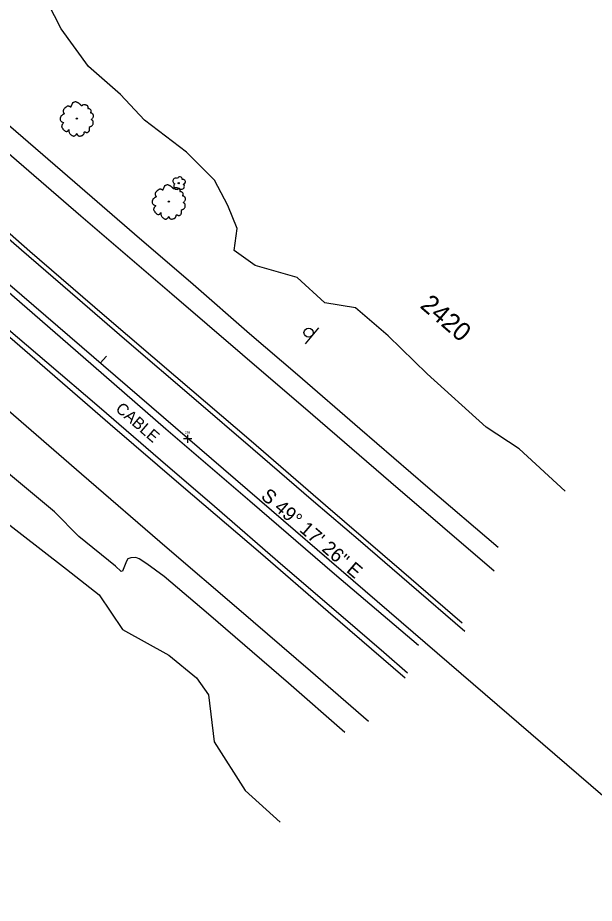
# Model space of a CAD drawing. Extents: x 2076109 to 2080761, y 592812 to 596750.
# Drawn here: x 2080011.7 to 2080260.2, y 593194 to 593575.6 of the extents above; entities that cross this region are included whole.
import ezdxf

# ---------------------------------------------------------------- set-up
doc = ezdxf.new("R2010")
doc.units = 0
for name, color, linetype in [('Default', 7, 'Continuous'), ('RD_EX_BldgApp', 7, 'Continuous'), ('RD_EX_GuardRail', 7, 'Continuous'), ('RD_EX_GuardRail_txCode', 7, 'Continuous'), ('RD_EX_Misc', 7, 'Continuous'), ('RD_EX_Road', 7, 'Continuous'), ('RD_EX_VEG', 7, 'Continuous'), ('RD_HC_Cl', 7, 'Continuous'), ('RD_HC_Data', 7, 'Continuous'), ('RD_HC_Data_Tic', 7, 'Continuous'), ('RD_HC_TX_Sta50', 7, 'Continuous')]:
    doc.layers.add(name, color=color, linetype=linetype)

msp = doc.modelspace()

# ---------------------------------------------------------------- linework, layer by layer
at = {"layer": 'Default'}
for p, q in [((2080084.9, 593395.9), (2080084.9, 593392.4)), ((2080084.9, 593395.9), (2080084.9, 593392.4)), ((2080086.65, 593394.15), (2080083.15, 593394.15)), ((2080086.65, 593394.15), (2080083.15, 593394.15))]:
    msp.add_line(p, q, dxfattribs=at)
at = {"layer": 'RD_EX_BldgApp'}
msp.add_line((2080135.68, 593435.15), (2080141.49, 593442.02), dxfattribs=at)
msp.add_line((2080135.68, 593435.15), (2080141.49, 593442.02), dxfattribs=at)
msp.add_circle((2080137.05, 593439.9), 2, dxfattribs=at)
msp.add_circle((2080137.05, 593439.9), 2, dxfattribs=at)
at = {"layer": 'RD_EX_GuardRail'}
msp.add_lwpolyline([(2080184.35, 593305.04), (2080148.2, 593335.86), (2080111.67, 593367.26), (2080075.44, 593398.3), (2080039.84, 593429.28), (2080003.46, 593460.74), (2079967.36, 593491.67), (2079919.17, 593532.83), (2079871.19, 593574.23), (2079835.53, 593605.02), (2079799.41, 593635.93), (2079763.16, 593666.95), (2079727.5, 593697.27), (2079690.37, 593729.2), (2079655.55, 593758.99), (2079608.01, 593799.67)], dxfattribs=at)
at = {"layer": 'RD_EX_Misc'}
for points in [[(2080217.04, 593337.18), (2080172.52, 593375.33), (2080138.87, 593404.33), (2080108.48, 593430.29), (2080078.14, 593456.52), (2080038.92, 593490.11), (2080009.05, 593515.98), (2079977.29, 593543.26), (2079946.15, 593570.28), (2079919.11, 593593.43), (2079890.41, 593617.97), (2079858.75, 593645.26), (2079821.86, 593677.15), (2079782.12, 593711.42), (2079735.64, 593751.71), (2079701.45, 593781.37), (2079664.35, 593813.72), (2079643.76, 593831.64)], [(2079627.11, 593812.28), (2079655.96, 593786.97), (2079692.98, 593754.86), (2079726.56, 593725.77), (2079758.83, 593697.63), (2079788.04, 593672.28), (2079811.24, 593652.3), (2079842, 593625.98), (2079868.07, 593603.53), (2079898.03, 593577.49), (2079923.97, 593555.11), (2079945.84, 593536.38), (2079972.92, 593513.01), (2079994.98, 593494.07), (2080016.85, 593475.02), (2080049.11, 593447.31), (2080079.81, 593420.95), (2080112.25, 593393.22), (2080144.25, 593365.64), (2080177.02, 593337.45), (2080203.16, 593314.91)], [(2080178.72, 593290.98), (2080145.52, 593319.67), (2080116.25, 593344.84), (2080082.12, 593374.03), (2080051.53, 593400.34), (2080021.2, 593426.66), (2079989.82, 593453.61), (2079954.27, 593484.21), (2079917.77, 593515.59), (2079872.88, 593554.03), (2079843.75, 593579.04), (2079811.01, 593607.11), (2079771.89, 593640.76), (2079736.28, 593671.46), (2079708.41, 593695.19), (2079678.65, 593720.6), (2079637.6, 593755.82), (2079606.82, 593782.2)], [(2079590.1, 593765.16), (2079617.13, 593742.26), (2079645.39, 593718.11), (2079673.76, 593693.67), (2079705.98, 593665.94), (2079741.28, 593635.42), (2079768.01, 593612.45), (2079794.32, 593589.74), (2079821.72, 593566.1), (2079850.25, 593541.52), (2079880.79, 593515.25), (2079909.32, 593490.67), (2079940.4, 593463.94), (2079966.11, 593441.94), (2079995.57, 593416.65), (2080039.13, 593379.08), (2080076.01, 593347.24), (2080106.97, 593320.7), (2080137.83, 593294.2), (2080162.8, 593272.51)]]:
    msp.add_lwpolyline(points, dxfattribs=at)
at = {"layer": 'RD_EX_Road'}
for points in [[(2079847.19, 593579.3), (2079876.99, 593553.77), (2079900.24, 593533.48), (2079923.68, 593513.62), (2079949.41, 593491.47), (2079974.36, 593470.03), (2079998.83, 593448.69), (2080024.15, 593427.25), (2080046.72, 593407.88), (2080073.17, 593385.13), (2080096.5, 593365.09), (2080125.99, 593339.59), (2080151.99, 593317.38), (2080169.44, 593302.21), (2080179.69, 593293.27)], [(2080204.43, 593311.21), (2080180.43, 593331.76), (2080159.45, 593349.86), (2080139.19, 593367.19), (2080113.07, 593389.68), (2080087.59, 593411.58), (2080058.73, 593436.21), (2080034.27, 593457.36), (2080013.24, 593475.51), (2079982.05, 593502.38), (2079952.67, 593527.69), (2079915.58, 593559.4), (2079891.77, 593580.17)], [(2079952.79, 593576.41), (2079973.53, 593558.52), (2079991.07, 593543.66), (2080010.86, 593526.69), (2080036.29, 593504.75), (2080061.97, 593482.54), (2080087.26, 593460.81), (2080111.58, 593439.6), (2080132.18, 593421.92), (2080159.11, 593398.54), (2080188.43, 593373.33), (2080218.73, 593347.44)], [(2080152.72, 593267.66), (2080128.39, 593288.81), (2080093.85, 593318.54), (2080074.78, 593334.89), (2080067.34, 593340.26), (2080064, 593342.46), (2080062.54, 593343.07), (2080060.4, 593342.84), (2080059.08, 593342.5), (2080058.49, 593341.44), (2080056.81, 593337.09), (2080056.21, 593336.92), (2080053.82, 593339.36), (2080038, 593352.02), (2080027.51, 593362.71), (2080013.69, 593374.25), (2079994.53, 593390.12)]]:
    msp.add_lwpolyline(points, dxfattribs=at)
at = {"layer": 'RD_EX_VEG'}
for points in [[(2080247.68, 593371.56), (2080227.73, 593389.81), (2080213.63, 593399.22), (2080188.12, 593422.2), (2080171.34, 593438.57), (2080157.25, 593450.56), (2080143.98, 593452.78), (2080132.06, 593463.64), (2080114, 593468.88), (2080104.89, 593475.28), (2080106.2, 593484.71), (2080102.2, 593494.65), (2080096.44, 593505.56), (2080084.44, 593517.6), (2080066.35, 593531.39), (2080055.91, 593542.46), (2080042.12, 593554.57), (2080030.41, 593570.81), (2080021.61, 593588.05), (2080015.74, 593597.76)], [(2079741.28, 593586.6), (2079759.63, 593573.33), (2079766.05, 593568.33), (2079784.04, 593551.85), (2079798.13, 593538.37), (2079815.23, 593521.73), (2079829.05, 593516.08), (2079860.88, 593485.4), (2079888.13, 593460.36), (2079900, 593443.24), (2079927, 593427.12), (2079947.52, 593409.93), (2079973.96, 593389.29), (2080002.41, 593361.36), (2080032.72, 593337.93), (2080046.73, 593326.92), (2080056.76, 593311.95), (2080076.73, 593300.98), (2080088.77, 593291.13), (2080093.96, 593283.85), (2080096.32, 593263.66), (2080109.67, 593242.67), (2080124.71, 593229.03)]]:
    msp.add_lwpolyline(points, dxfattribs=at)
for centre, radius in [((2080037.12, 593532.12), 0.25), ((2080037.12, 593532.12), 0.25), ((2080037.1, 593532.12), 0.0001), ((2080037.1, 593532.12), 0.0001), ((2080081.06, 593504.32), 0.25), ((2080081.06, 593504.32), 0.25), ((2080076.77, 593496.36), 0.25), ((2080076.77, 593496.36), 0.25), ((2080076.75, 593496.35), 0.0001), ((2080076.75, 593496.35), 0.0001)]:
    msp.add_circle(centre, radius, dxfattribs=at)
for centre, radius, start, end in [((2080079.78, 593505.22), 1.26, 55.6193, 253.9015), ((2080079.78, 593505.22), 1.26, 55.6193, 253.9015), ((2080081.53, 593505.96), 1.08, 354.1438, 163.9235), ((2080081.53, 593505.96), 1.08, 354.1438, 163.9235), ((2080082.97, 593504.92), 0.995, 267.9301, 111.2143), ((2080082.97, 593504.92), 0.995, 267.9301, 111.2143), ((2080080.2, 593502.95), 1.32, 126.0502, 324.9265), ((2080080.2, 593502.95), 1.32, 126.0502, 324.9265), ((2080082.27, 593502.9), 1.22, 215.7342, 57.2722), ((2080082.27, 593502.9), 1.22, 215.7342, 57.2722)]:
    msp.add_arc(centre, radius, start, end, dxfattribs=at)
for points in [[(2080041.91, 593537.46), (2080041.7, 593537.68), (2080041.39, 593537.81), (2080041.13, 593537.9), (2080040.91, 593537.99), (2080040.68, 593538.06), (2080040.34, 593538.13), (2080040.03, 593538.12), (2080039.78, 593538.01), (2080039.59, 593537.88), (2080039.37, 593537.7), (2080039.26, 593537.57), (2080039.15, 593537.63), (2080039.05, 593537.75), (2080038.91, 593537.97), (2080038.72, 593538.13), (2080038.53, 593538.3), (2080038.25, 593538.51), (2080037.99, 593538.73), (2080037.75, 593538.88), (2080037.47, 593539.05), (2080037.1, 593539.2), (2080036.76, 593539.34), (2080036.37, 593539.34), (2080035.87, 593539.15), (2080035.54, 593538.96), (2080035.27, 593538.87), (2080035.09, 593538.43), (2080034.99, 593538.05), (2080034.88, 593537.89), (2080034.66, 593537.52), (2080034.59, 593537.28), (2080034.55, 593537.05), (2080034.48, 593537.08), (2080034.16, 593537.29), (2080033.87, 593537.41), (2080033.4, 593537.51), (2080033.08, 593537.49), (2080032.79, 593537.31), (2080032.55, 593537.06), (2080032.34, 593536.98), (2080032.1, 593536.82), (2080032.04, 593536.78), (2080031.79, 593536.56), (2080031.57, 593536.16), (2080031.36, 593535.88), (2080031.31, 593535.62), (2080031.3, 593535.39), (2080031.27, 593535.09), (2080031.43, 593534.66), (2080031.61, 593534.37), (2080031.74, 593534.22), (2080031.28, 593533.96), (2080031.02, 593533.73), (2080030.66, 593533.51), (2080030.61, 593533.45), (2080030.27, 593533.12), (2080030.17, 593532.78), (2080029.98, 593532.45), (2080029.96, 593532.16), (2080029.97, 593531.75), (2080030.07, 593531.37), (2080030.37, 593530.95), (2080030.69, 593530.71), (2080031.24, 593530.46), (2080031.48, 593530.36), (2080031.34, 593530.24), (2080031.12, 593529.94), (2080030.84, 593529.62), (2080030.74, 593529.28), (2080030.64, 593529), (2080030.59, 593528.72), (2080030.68, 593528.33), (2080030.94, 593528.02), (2080031.16, 593527.62), (2080031.45, 593527.27), (2080031.81, 593526.93), (2080032.37, 593526.65), (2080032.66, 593526.56), (2080032.85, 593526.63), (2080033.24, 593526.78), (2080033.35, 593526.99), (2080033.76, 593527.42), (2080033.72, 593527.23), (2080033.63, 593526.85), (2080033.81, 593526.29), (2080034, 593525.9), (2080034.26, 593525.48), (2080034.44, 593525.22), (2080034.85, 593524.97), (2080035.18, 593524.78), (2080035.54, 593524.63), (2080035.95, 593524.64), (2080036.26, 593524.74), (2080036.48, 593524.91), (2080036.78, 593525.15), (2080036.93, 593525.25)], [(2080041.91, 593537.46), (2080041.7, 593537.68), (2080041.39, 593537.81), (2080041.13, 593537.9), (2080040.91, 593537.99), (2080040.68, 593538.06), (2080040.34, 593538.13), (2080040.03, 593538.12), (2080039.78, 593538.01), (2080039.59, 593537.88), (2080039.37, 593537.7), (2080039.26, 593537.57), (2080039.15, 593537.63), (2080039.05, 593537.75), (2080038.91, 593537.97), (2080038.72, 593538.13), (2080038.53, 593538.3), (2080038.25, 593538.51), (2080037.99, 593538.73), (2080037.75, 593538.88), (2080037.47, 593539.05), (2080037.1, 593539.2), (2080036.76, 593539.34), (2080036.37, 593539.34), (2080035.87, 593539.15), (2080035.54, 593538.96), (2080035.27, 593538.87), (2080035.09, 593538.43), (2080034.99, 593538.05), (2080034.88, 593537.89), (2080034.66, 593537.52), (2080034.59, 593537.28), (2080034.55, 593537.05), (2080034.48, 593537.08), (2080034.16, 593537.29), (2080033.87, 593537.41), (2080033.4, 593537.51), (2080033.08, 593537.49), (2080032.79, 593537.31), (2080032.55, 593537.06), (2080032.34, 593536.98), (2080032.1, 593536.82), (2080032.04, 593536.78), (2080031.79, 593536.56), (2080031.57, 593536.16), (2080031.36, 593535.88), (2080031.31, 593535.62), (2080031.3, 593535.39), (2080031.27, 593535.09), (2080031.43, 593534.66), (2080031.61, 593534.37), (2080031.74, 593534.22), (2080031.28, 593533.96), (2080031.02, 593533.73), (2080030.66, 593533.51), (2080030.61, 593533.45), (2080030.27, 593533.12), (2080030.17, 593532.78), (2080029.98, 593532.45), (2080029.96, 593532.16), (2080029.97, 593531.75), (2080030.07, 593531.37), (2080030.37, 593530.95), (2080030.69, 593530.71), (2080031.24, 593530.46), (2080031.48, 593530.36), (2080031.34, 593530.24), (2080031.12, 593529.94), (2080030.84, 593529.62), (2080030.74, 593529.28), (2080030.64, 593529), (2080030.59, 593528.72), (2080030.68, 593528.33), (2080030.94, 593528.02), (2080031.16, 593527.62), (2080031.45, 593527.27), (2080031.81, 593526.93), (2080032.37, 593526.65), (2080032.66, 593526.56), (2080032.85, 593526.63), (2080033.24, 593526.78), (2080033.35, 593526.99), (2080033.76, 593527.42), (2080033.72, 593527.23), (2080033.63, 593526.85), (2080033.81, 593526.29), (2080034, 593525.9), (2080034.26, 593525.48), (2080034.44, 593525.22), (2080034.85, 593524.97), (2080035.18, 593524.78), (2080035.54, 593524.63), (2080035.95, 593524.64), (2080036.26, 593524.74), (2080036.48, 593524.91), (2080036.78, 593525.15), (2080036.93, 593525.25)], [(2080036.93, 593525.25), (2080036.99, 593525.43), (2080037.12, 593525.65), (2080037.16, 593525.58), (2080037.26, 593525.43), (2080037.38, 593525.15), (2080037.5, 593524.95), (2080037.77, 593524.76), (2080038.04, 593524.65), (2080038.56, 593524.57), (2080039.08, 593524.75), (2080039.55, 593524.87), (2080039.82, 593525.07), (2080039.93, 593525.27), (2080040.23, 593525.66), (2080040.25, 593525.98), (2080040.29, 593526.11), (2080040.48, 593526.48), (2080040.57, 593526.47), (2080040.81, 593526.32), (2080041.17, 593526.17), (2080041.46, 593526.09), (2080041.75, 593526.07), (2080041.95, 593526.2), (2080042.19, 593526.51), (2080042.49, 593526.78), (2080042.53, 593526.95), (2080042.55, 593527.13), (2080042.63, 593527.33), (2080042.61, 593527.54), (2080042.64, 593527.72), (2080042.63, 593527.86), (2080042.63, 593528.05), (2080042.58, 593528.26), (2080042.5, 593528.4), (2080042.56, 593528.54), (2080042.8, 593528.6), (2080042.9, 593528.64), (2080043.07, 593528.79), (2080043.47, 593528.91), (2080043.77, 593529.18), (2080044.01, 593529.53), (2080044.15, 593529.78), (2080044.22, 593530.08), (2080044.23, 593530.4), (2080044.25, 593530.62), (2080044.2, 593530.82), (2080044.03, 593531.13), (2080043.88, 593531.33), (2080043.61, 593531.56), (2080043.49, 593531.73), (2080043.55, 593531.75), (2080043.64, 593531.86), (2080043.82, 593532.07), (2080044.06, 593532.46), (2080044.27, 593532.94), (2080044.29, 593532.96), (2080044.38, 593533.21), (2080044.34, 593533.51), (2080044.27, 593533.7), (2080044.2, 593533.92), (2080044.03, 593534.11), (2080043.8, 593534.3), (2080043.56, 593534.44), (2080043.35, 593534.5), (2080043.13, 593534.52), (2080043.17, 593534.68), (2080043.29, 593534.97), (2080043.35, 593535.12), (2080043.35, 593535.35), (2080043.32, 593535.65), (2080043.06, 593536.04), (2080042.53, 593536.39), (2080042.18, 593536.43), (2080041.95, 593536.4), (2080041.99, 593536.53), (2080041.97, 593536.81), (2080042.01, 593537.01), (2080041.96, 593537.22), (2080041.91, 593537.39), (2080041.87, 593537.49)], [(2080036.93, 593525.25), (2080036.99, 593525.43), (2080037.12, 593525.65), (2080037.16, 593525.58), (2080037.26, 593525.43), (2080037.38, 593525.15), (2080037.5, 593524.95), (2080037.77, 593524.76), (2080038.04, 593524.65), (2080038.56, 593524.57), (2080039.08, 593524.75), (2080039.55, 593524.87), (2080039.82, 593525.07), (2080039.93, 593525.27), (2080040.23, 593525.66), (2080040.25, 593525.98), (2080040.29, 593526.11), (2080040.48, 593526.48), (2080040.57, 593526.47), (2080040.81, 593526.32), (2080041.17, 593526.17), (2080041.46, 593526.09), (2080041.75, 593526.07), (2080041.95, 593526.2), (2080042.19, 593526.51), (2080042.49, 593526.78), (2080042.53, 593526.95), (2080042.55, 593527.13), (2080042.63, 593527.33), (2080042.61, 593527.54), (2080042.64, 593527.72), (2080042.63, 593527.86), (2080042.63, 593528.05), (2080042.58, 593528.26), (2080042.5, 593528.4), (2080042.56, 593528.54), (2080042.8, 593528.6), (2080042.9, 593528.64), (2080043.07, 593528.79), (2080043.47, 593528.91), (2080043.77, 593529.18), (2080044.01, 593529.53), (2080044.15, 593529.78), (2080044.22, 593530.08), (2080044.23, 593530.4), (2080044.25, 593530.62), (2080044.2, 593530.82), (2080044.03, 593531.13), (2080043.88, 593531.33), (2080043.61, 593531.56), (2080043.49, 593531.73), (2080043.55, 593531.75), (2080043.64, 593531.86), (2080043.82, 593532.07), (2080044.06, 593532.46), (2080044.27, 593532.94), (2080044.29, 593532.96), (2080044.38, 593533.21), (2080044.34, 593533.51), (2080044.27, 593533.7), (2080044.2, 593533.92), (2080044.03, 593534.11), (2080043.8, 593534.3), (2080043.56, 593534.44), (2080043.35, 593534.5), (2080043.13, 593534.52), (2080043.17, 593534.68), (2080043.29, 593534.97), (2080043.35, 593535.12), (2080043.35, 593535.35), (2080043.32, 593535.65), (2080043.06, 593536.04), (2080042.53, 593536.39), (2080042.18, 593536.43), (2080041.95, 593536.4), (2080041.99, 593536.53), (2080041.97, 593536.81), (2080042.01, 593537.01), (2080041.96, 593537.22), (2080041.91, 593537.39), (2080041.87, 593537.49)], [(2080081.56, 593501.69), (2080081.35, 593501.91), (2080081.04, 593502.04), (2080080.78, 593502.13), (2080080.56, 593502.22), (2080080.33, 593502.29), (2080079.99, 593502.36), (2080079.69, 593502.35), (2080079.43, 593502.25), (2080079.24, 593502.11), (2080079.03, 593501.93), (2080078.91, 593501.8), (2080078.8, 593501.86), (2080078.7, 593501.98), (2080078.56, 593502.2), (2080078.37, 593502.36), (2080078.18, 593502.53), (2080077.9, 593502.74), (2080077.64, 593502.97), (2080077.4, 593503.11), (2080077.12, 593503.28), (2080076.75, 593503.43), (2080076.41, 593503.57), (2080076.02, 593503.57), (2080075.52, 593503.38), (2080075.19, 593503.19), (2080074.92, 593503.1), (2080074.74, 593502.67), (2080074.64, 593502.29), (2080074.53, 593502.12), (2080074.31, 593501.75), (2080074.24, 593501.51), (2080074.2, 593501.28), (2080074.13, 593501.31), (2080073.81, 593501.52), (2080073.52, 593501.64), (2080073.05, 593501.75), (2080072.73, 593501.72), (2080072.45, 593501.54), (2080072.2, 593501.29), (2080071.99, 593501.21), (2080071.75, 593501.05), (2080071.69, 593501.01), (2080071.44, 593500.79), (2080071.22, 593500.39), (2080071.01, 593500.11), (2080070.96, 593499.86), (2080070.95, 593499.63), (2080070.92, 593499.32), (2080071.08, 593498.89), (2080071.26, 593498.6), (2080071.39, 593498.45), (2080070.94, 593498.19), (2080070.67, 593497.96), (2080070.31, 593497.74), (2080070.26, 593497.68), (2080069.92, 593497.35), (2080069.82, 593497.01), (2080069.63, 593496.68), (2080069.61, 593496.39), (2080069.63, 593495.99), (2080069.72, 593495.6), (2080070.02, 593495.18), (2080070.34, 593494.94), (2080070.89, 593494.7), (2080071.13, 593494.59), (2080070.99, 593494.47), (2080070.77, 593494.17), (2080070.49, 593493.85), (2080070.39, 593493.51), (2080070.29, 593493.23), (2080070.24, 593492.95), (2080070.34, 593492.56), (2080070.59, 593492.25), (2080070.81, 593491.86), (2080071.1, 593491.5), (2080071.47, 593491.16), (2080072.02, 593490.88), (2080072.31, 593490.8), (2080072.5, 593490.86), (2080072.89, 593491.02), (2080073, 593491.22), (2080073.41, 593491.66), (2080073.37, 593491.46), (2080073.28, 593491.08), (2080073.46, 593490.52), (2080073.65, 593490.13), (2080073.91, 593489.71), (2080074.09, 593489.45), (2080074.5, 593489.2), (2080074.83, 593489.01), (2080075.19, 593488.86), (2080075.6, 593488.87), (2080075.91, 593488.97), (2080076.13, 593489.14), (2080076.43, 593489.38), (2080076.58, 593489.48)], [(2080081.56, 593501.69), (2080081.35, 593501.91), (2080081.04, 593502.04), (2080080.78, 593502.13), (2080080.56, 593502.22), (2080080.33, 593502.29), (2080079.99, 593502.36), (2080079.69, 593502.35), (2080079.43, 593502.25), (2080079.24, 593502.11), (2080079.03, 593501.93), (2080078.91, 593501.8), (2080078.8, 593501.86), (2080078.7, 593501.98), (2080078.56, 593502.2), (2080078.37, 593502.36), (2080078.18, 593502.53), (2080077.9, 593502.74), (2080077.64, 593502.97), (2080077.4, 593503.11), (2080077.12, 593503.28), (2080076.75, 593503.43), (2080076.41, 593503.57), (2080076.02, 593503.57), (2080075.52, 593503.38), (2080075.19, 593503.19), (2080074.92, 593503.1), (2080074.74, 593502.67), (2080074.64, 593502.29), (2080074.53, 593502.12), (2080074.31, 593501.75), (2080074.24, 593501.51), (2080074.2, 593501.28), (2080074.13, 593501.31), (2080073.81, 593501.52), (2080073.52, 593501.64), (2080073.05, 593501.75), (2080072.73, 593501.72), (2080072.45, 593501.54), (2080072.2, 593501.29), (2080071.99, 593501.21), (2080071.75, 593501.05), (2080071.69, 593501.01), (2080071.44, 593500.79), (2080071.22, 593500.39), (2080071.01, 593500.11), (2080070.96, 593499.86), (2080070.95, 593499.63), (2080070.92, 593499.32), (2080071.08, 593498.89), (2080071.26, 593498.6), (2080071.39, 593498.45), (2080070.94, 593498.19), (2080070.67, 593497.96), (2080070.31, 593497.74), (2080070.26, 593497.68), (2080069.92, 593497.35), (2080069.82, 593497.01), (2080069.63, 593496.68), (2080069.61, 593496.39), (2080069.63, 593495.99), (2080069.72, 593495.6), (2080070.02, 593495.18), (2080070.34, 593494.94), (2080070.89, 593494.7), (2080071.13, 593494.59), (2080070.99, 593494.47), (2080070.77, 593494.17), (2080070.49, 593493.85), (2080070.39, 593493.51), (2080070.29, 593493.23), (2080070.24, 593492.95), (2080070.34, 593492.56), (2080070.59, 593492.25), (2080070.81, 593491.86), (2080071.1, 593491.5), (2080071.47, 593491.16), (2080072.02, 593490.88), (2080072.31, 593490.8), (2080072.5, 593490.86), (2080072.89, 593491.02), (2080073, 593491.22), (2080073.41, 593491.66), (2080073.37, 593491.46), (2080073.28, 593491.08), (2080073.46, 593490.52), (2080073.65, 593490.13), (2080073.91, 593489.71), (2080074.09, 593489.45), (2080074.5, 593489.2), (2080074.83, 593489.01), (2080075.19, 593488.86), (2080075.6, 593488.87), (2080075.91, 593488.97), (2080076.13, 593489.14), (2080076.43, 593489.38), (2080076.58, 593489.48)], [(2080076.58, 593489.48), (2080076.64, 593489.66), (2080076.77, 593489.88), (2080076.81, 593489.81), (2080076.91, 593489.66), (2080077.03, 593489.39), (2080077.15, 593489.18), (2080077.42, 593488.99), (2080077.69, 593488.88), (2080078.21, 593488.8), (2080078.73, 593488.98), (2080079.2, 593489.1), (2080079.47, 593489.3), (2080079.58, 593489.5), (2080079.88, 593489.89), (2080079.9, 593490.21), (2080079.94, 593490.34), (2080080.13, 593490.71), (2080080.22, 593490.7), (2080080.46, 593490.56), (2080080.82, 593490.41), (2080081.11, 593490.32), (2080081.4, 593490.31), (2080081.6, 593490.43), (2080081.84, 593490.75), (2080082.14, 593491.02), (2080082.18, 593491.18), (2080082.21, 593491.36), (2080082.28, 593491.56), (2080082.26, 593491.77), (2080082.29, 593491.95), (2080082.28, 593492.09), (2080082.28, 593492.28), (2080082.23, 593492.49), (2080082.15, 593492.63), (2080082.21, 593492.77), (2080082.45, 593492.83), (2080082.56, 593492.87), (2080082.72, 593493.02), (2080083.12, 593493.14), (2080083.42, 593493.41), (2080083.66, 593493.77), (2080083.8, 593494.01), (2080083.87, 593494.31), (2080083.88, 593494.63), (2080083.9, 593494.85), (2080083.85, 593495.06), (2080083.68, 593495.36), (2080083.53, 593495.56), (2080083.26, 593495.79), (2080083.15, 593495.96), (2080083.2, 593495.98), (2080083.29, 593496.1), (2080083.47, 593496.3), (2080083.71, 593496.69), (2080083.93, 593497.17), (2080083.94, 593497.19), (2080084.03, 593497.44), (2080083.99, 593497.74), (2080083.92, 593497.93), (2080083.85, 593498.16), (2080083.68, 593498.34), (2080083.45, 593498.53), (2080083.21, 593498.68), (2080083, 593498.73), (2080082.78, 593498.75), (2080082.82, 593498.91), (2080082.94, 593499.21), (2080083, 593499.35), (2080083.01, 593499.58), (2080082.97, 593499.88), (2080082.71, 593500.27), (2080082.19, 593500.62), (2080081.83, 593500.67), (2080081.6, 593500.63), (2080081.64, 593500.76), (2080081.62, 593501.04), (2080081.66, 593501.24), (2080081.61, 593501.45), (2080081.56, 593501.62), (2080081.52, 593501.72)], [(2080076.58, 593489.48), (2080076.64, 593489.66), (2080076.77, 593489.88), (2080076.81, 593489.81), (2080076.91, 593489.66), (2080077.03, 593489.39), (2080077.15, 593489.18), (2080077.42, 593488.99), (2080077.69, 593488.88), (2080078.21, 593488.8), (2080078.73, 593488.98), (2080079.2, 593489.1), (2080079.47, 593489.3), (2080079.58, 593489.5), (2080079.88, 593489.89), (2080079.9, 593490.21), (2080079.94, 593490.34), (2080080.13, 593490.71), (2080080.22, 593490.7), (2080080.46, 593490.56), (2080080.82, 593490.41), (2080081.11, 593490.32), (2080081.4, 593490.31), (2080081.6, 593490.43), (2080081.84, 593490.75), (2080082.14, 593491.02), (2080082.18, 593491.18), (2080082.21, 593491.36), (2080082.28, 593491.56), (2080082.26, 593491.77), (2080082.29, 593491.95), (2080082.28, 593492.09), (2080082.28, 593492.28), (2080082.23, 593492.49), (2080082.15, 593492.63), (2080082.21, 593492.77), (2080082.45, 593492.83), (2080082.56, 593492.87), (2080082.72, 593493.02), (2080083.12, 593493.14), (2080083.42, 593493.41), (2080083.66, 593493.77), (2080083.8, 593494.01), (2080083.87, 593494.31), (2080083.88, 593494.63), (2080083.9, 593494.85), (2080083.85, 593495.06), (2080083.68, 593495.36), (2080083.53, 593495.56), (2080083.26, 593495.79), (2080083.15, 593495.96), (2080083.2, 593495.98), (2080083.29, 593496.1), (2080083.47, 593496.3), (2080083.71, 593496.69), (2080083.93, 593497.17), (2080083.94, 593497.19), (2080084.03, 593497.44), (2080083.99, 593497.74), (2080083.92, 593497.93), (2080083.85, 593498.16), (2080083.68, 593498.34), (2080083.45, 593498.53), (2080083.21, 593498.68), (2080083, 593498.73), (2080082.78, 593498.75), (2080082.82, 593498.91), (2080082.94, 593499.21), (2080083, 593499.35), (2080083.01, 593499.58), (2080082.97, 593499.88), (2080082.71, 593500.27), (2080082.19, 593500.62), (2080081.83, 593500.67), (2080081.6, 593500.63), (2080081.64, 593500.76), (2080081.62, 593501.04), (2080081.66, 593501.24), (2080081.61, 593501.45), (2080081.56, 593501.62), (2080081.52, 593501.72)]]:
    msp.add_spline(points, degree=3, dxfattribs=at)
at = {"layer": 'RD_HC_Cl'}
msp.add_line((2079511.94, 593887.33), (2080761.16, 592812.48), dxfattribs=at)
at = {"layer": 'RD_HC_Data_Tic'}
msp.add_line((2080047.26, 593426.73), (2080049.87, 593429.76), dxfattribs=at)
msp.add_line((2080047.26, 593426.73), (2080049.87, 593429.76), dxfattribs=at)

# ---------------------------------------------------------------- texts
at = {"layer": 'Default'}
msp.add_text('259', height=1, dxfattribs=at).set_placement((2080083.72, 593396.35))
msp.add_text('259', height=1, dxfattribs=at).set_placement((2080083.72, 593396.35))
at = {"layer": 'RD_EX_GuardRail_txCode'}
msp.add_text('CABLE', height=5, rotation=319.1675, dxfattribs=at).set_placement((2080053.46, 593406.52))
msp.add_text('CABLE', height=5, rotation=319.1675, dxfattribs=at).set_placement((2080053.46, 593406.52))
at = {"layer": 'RD_HC_Data'}
msp.add_text('S 49%%d 17\' 26" E', height=6, rotation=319.2904, dxfattribs=at).set_placement((2080116.09, 593368.83))
at = {"layer": 'RD_HC_TX_Sta50'}
msp.add_text('2420', height=8, rotation=319.2904, dxfattribs=at).set_placement((2080184.66, 593450.99))

doc.saveas('drawing.dxf')
